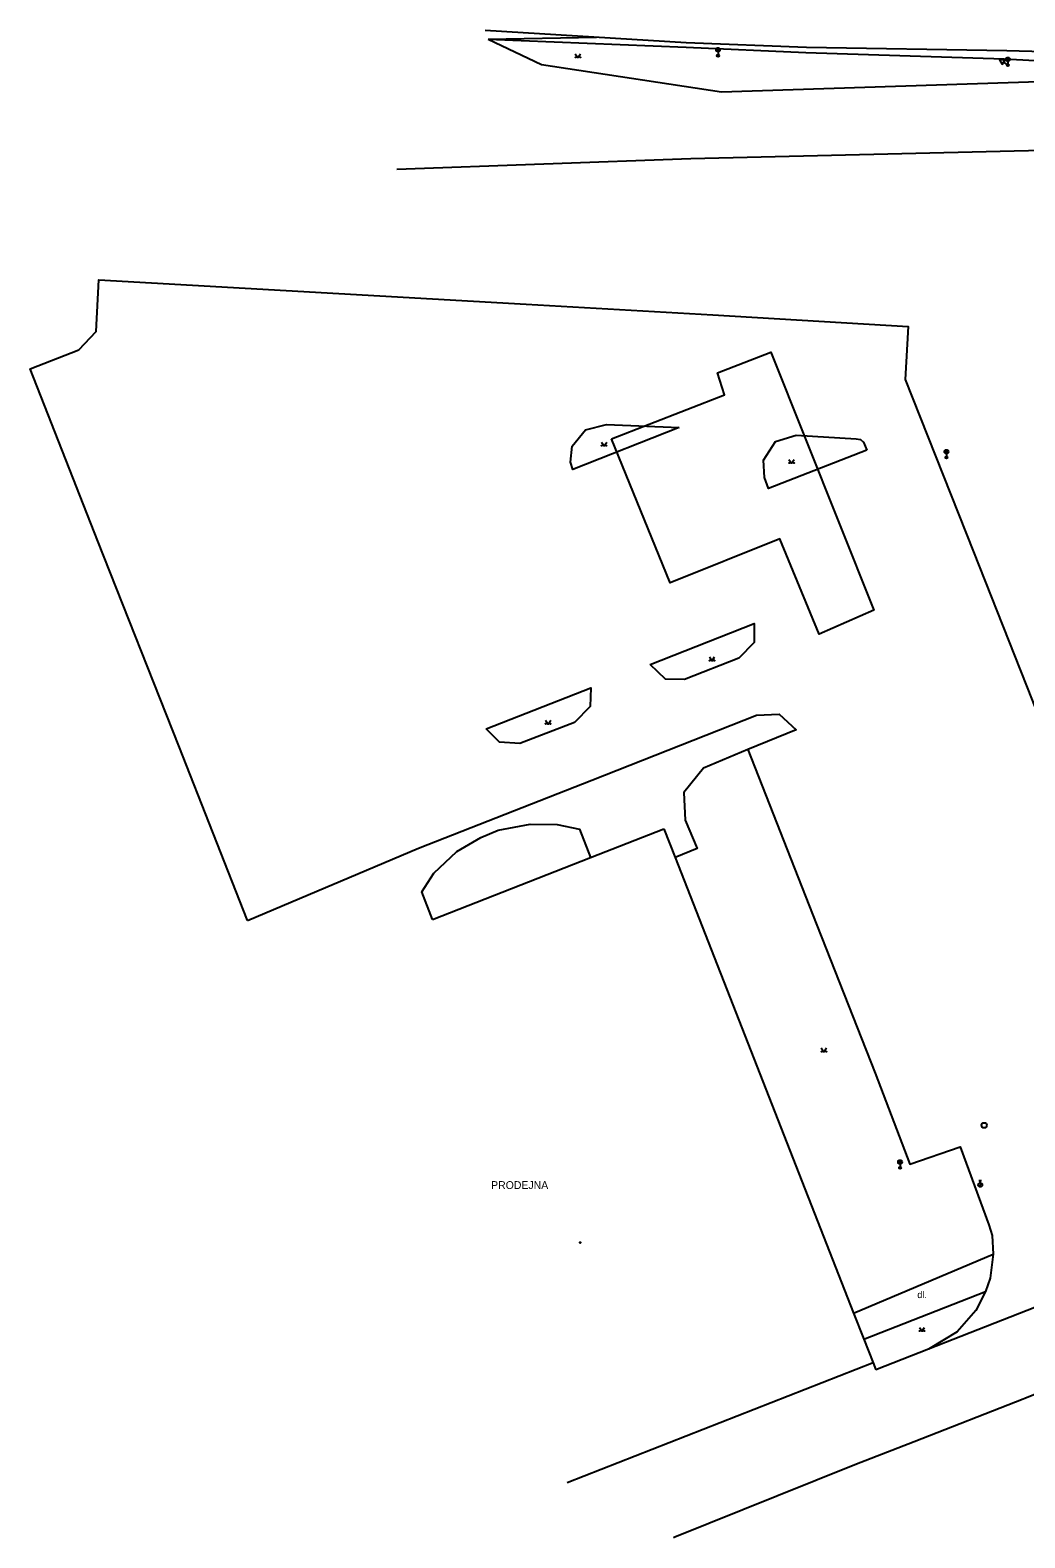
# Model space of a CAD drawing. Extents: x -602419 to -601554, y -1162937 to -1162362.
# Drawn here: x -602409.7 to -602314.6, y -1162869.2 to -1162725.1 of the extents above; entities that cross this region are included whole.
import ezdxf

# ---------------------------------------------------------------- set-up
doc = ezdxf.new("R2010")
doc.units = 0
doc.layers.add('Podklad', color=7, linetype='Continuous')

msp = doc.modelspace()

# ---------------------------------------------------------------- linework, layer by layer
at = {"layer": 'Podklad'}
for p, q in [((-602344.0925, -1162727.1), (-602343.8275, -1162726.835)), ((-602344.0925, -1162726.835), (-602343.8275, -1162727.1)), ((-602343.96, -1162727.155), (-602343.96, -1162727.53)), ((-602316.6789, -1162728.1659), (-602316.25, -1162728.44)), ((-602316.3825, -1162728.01), (-602316.1175, -1162727.745)), ((-602316.3825, -1162727.745), (-602316.1175, -1162728.01)), ((-602316.25, -1162728.065), (-602316.25, -1162728.44)), ((-602322.2625, -1162765.52), (-602321.9975, -1162765.255)), ((-602322.2625, -1162765.255), (-602321.9975, -1162765.52)), ((-602322.13, -1162765.575), (-602322.13, -1162765.95)), ((-602326.6925, -1162833.43), (-602326.4275, -1162833.165)), ((-602326.6925, -1162833.165), (-602326.4275, -1162833.43)), ((-602326.56, -1162833.485), (-602326.56, -1162833.86)), ((-602319.019, -1162835.626), (-602318.754, -1162835.361)), ((-602319.015, -1162835.0525), (-602318.765, -1162835.0525)), ((-602318.89, -1162835.3025), (-602318.89, -1162835.0525))]:
    msp.add_line(p, q, dxfattribs=at)
for points in [[(-602366.2199, -1162725.09), (-602346.99, -1162726.28), (-602335.5, -1162726.7199), (-602316.36, -1162727.02), (-602312.77, -1162727.14), (-602310.06, -1162728.28), (-602308.75, -1162729.84)], [(-602309.36, -1162729.86), (-602311.21, -1162728.65), (-602313.63, -1162728.03), (-602316.6, -1162727.87), (-602335.56, -1162727.26), (-602347, -1162726.75), (-602365.93, -1162725.9699)], [(-602365.9155, -1162725.9599), (-602355.5696, -1162725.7491)], [(-602365.9155, -1162725.9599), (-602360.83, -1162728.3839), (-602343.64, -1162730.9839), (-602309.36, -1162729.8599), (-602308.75, -1162729.84)], [(-602357.6, -1162727.3449), (-602357.35, -1162727.7199), (-602357.1, -1162727.3449)], [(-602304.89, -1162736.39), (-602346.56, -1162737.4)], [(-602346.56, -1162737.4), (-602374.65, -1162738.4)], [(-602388.93, -1162810.2), (-602395.51, -1162793.5), (-602403.24, -1162773.94), (-602409.71, -1162757.48), (-602405.07, -1162755.65), (-602403.4, -1162753.9), (-602403.15, -1162748.96), (-602362.29, -1162751.3), (-602344.45, -1162752.32), (-602325.79, -1162753.42), (-602326.07, -1162758.48), (-602319.53, -1162774.95), (-602313.93, -1162789.1599), (-602309.68, -1162800.1599), (-602304.38, -1162813.56), (-602300.54, -1162823.33)], [(-602354.13, -1162764.17), (-602343.33, -1162759.96), (-602344.02, -1162757.84), (-602338.9, -1162755.88), (-602329.05, -1162780.53), (-602334.3, -1162782.83), (-602338.04, -1162773.72), (-602348.54, -1162777.93), (-602354.13, -1162764.17)], [(-602347.67, -1162763.09), (-602357.83, -1162767.1), (-602358.07, -1162766.4), (-602357.9, -1162764.86), (-602356.64, -1162763.3), (-602354.63, -1162762.8), (-602347.67, -1162763.09)], [(-602329.7199, -1162765.26), (-602339.12, -1162768.9), (-602339.53, -1162767.86), (-602339.6, -1162766.2), (-602338.45, -1162764.42), (-602336.49, -1162763.8), (-602330.75, -1162764.1599), (-602330.34, -1162764.24), (-602330.05, -1162764.48), (-602329.7199, -1162765.26)], [(-602355.1, -1162764.465), (-602354.85, -1162764.84), (-602354.6, -1162764.465)], [(-602337.18, -1162766.125), (-602336.93, -1162766.5), (-602336.68, -1162766.125)], [(-602350.45, -1162785.7199), (-602340.5, -1162781.8), (-602340.5, -1162783.64), (-602341.96, -1162785.12), (-602347.1599, -1162787.1599), (-602348.98, -1162787.14), (-602350.45, -1162785.7199)], [(-602344.78, -1162785.005), (-602344.53, -1162785.38), (-602344.28, -1162785.005)], [(-602366.13, -1162791.88), (-602356.13, -1162787.96), (-602356.18, -1162789.76), (-602357.68, -1162791.28), (-602362.9, -1162793.28), (-602364.85, -1162793.1599), (-602366.13, -1162791.88)], [(-602388.93, -1162810.2), (-602372.6, -1162803.28), (-602356.02, -1162796.78), (-602340.27, -1162790.58), (-602338.12, -1162790.48), (-602336.5, -1162791.98), (-602341.12, -1162793.86)], [(-602360.45, -1162791.055), (-602360.2, -1162791.43), (-602359.95, -1162791.055)], [(-602341.12, -1162793.86), (-602345.34, -1162795.64), (-602347.23, -1162797.98), (-602347.09, -1162800.62), (-602345.95, -1162803.34), (-602348.05, -1162804.2)], [(-602341.12, -1162793.86), (-602334.94, -1162809.6), (-602328.95, -1162824.81), (-602325.64, -1162833.5), (-602320.82, -1162831.84), (-602318.07, -1162839.31), (-602317.77, -1162840.31), (-602317.6599, -1162842.12)], [(-602371.24, -1162810.13), (-602372.27, -1162807.47), (-602371.12, -1162805.7), (-602368.92, -1162803.62), (-602366.62, -1162802.26), (-602364.97, -1162801.56), (-602361.92, -1162800.99), (-602359.34, -1162801.04), (-602357.19, -1162801.47), (-602356.16, -1162804.2)], [(-602356.16, -1162804.2), (-602349.13, -1162801.44)], [(-602349.13, -1162801.44), (-602348.05, -1162804.2)], [(-602371.24, -1162810.13), (-602356.16, -1162804.2)], [(-602348.05, -1162804.2), (-602331, -1162847.74)], [(-602334.09, -1162822.395), (-602333.84, -1162822.77), (-602333.59, -1162822.395)], [(-602331, -1162847.74), (-602317.6599, -1162842.12)], [(-602300.26, -1162841.94), (-602323.84, -1162851.19)], [(-602317.6599, -1162842.12), (-602317.93, -1162844.4)], [(-602317.93, -1162844.4), (-602318.39, -1162845.69)], [(-602291.4, -1162846.37), (-602291.67, -1162846.5), (-602291.63, -1162846.58), (-602295.39, -1162848.31), (-602307.21, -1162852.94), (-602312.92, -1162855.22), (-602314.63, -1162855.9), (-602314.79, -1162855.96), (-602325.2, -1162860.06), (-602330.89, -1162862.26), (-602338.35, -1162865.25), (-602348.1, -1162869.18), (-602348.22, -1162869.23)], [(-602330.02, -1162850.25), (-602318.39, -1162845.69)], [(-602318.39, -1162845.69), (-602319.3, -1162847.48), (-602321.09, -1162849.54), (-602323.84, -1162851.19), (-602328.87, -1162853.18)], [(-602331, -1162847.74), (-602330.02, -1162850.25)], [(-602324.71, -1162849.105), (-602324.46, -1162849.48), (-602324.21, -1162849.105)], [(-602330.02, -1162850.25), (-602329.13, -1162852.51)], [(-602329.13, -1162852.51), (-602358.38, -1162863.96)], [(-602329.13, -1162852.51), (-602328.87, -1162853.18)]]:
    msp.add_lwpolyline(points, dxfattribs=at)
msp.add_lwpolyline([(-602316.8135, -1162728.3766), (-602316.5443, -1162727.9553), (-602317.0438, -1162727.9328)], close=True, dxfattribs=at)
for centre, radius in [((-602343.96, -1162726.9675), 0.1875), ((-602357.5751, -1162727.6948), 0.025), ((-602357.1254, -1162727.6948), 0.025), ((-602343.96, -1162727.53), 0.1), ((-602343.96, -1162727.53), 0.0723), ((-602343.96, -1162727.53), 0.0438), ((-602316.25, -1162727.8775), 0.1875), ((-602316.25, -1162728.44), 0.1), ((-602316.25, -1162728.44), 0.0723), ((-602316.25, -1162728.44), 0.0438), ((-602355.0751, -1162764.8149), 0.025), ((-602354.6254, -1162764.8149), 0.025), ((-602322.13, -1162765.3875), 0.1875), ((-602337.1551, -1162766.4749), 0.025), ((-602336.7054, -1162766.4749), 0.025), ((-602322.13, -1162765.95), 0.1), ((-602322.13, -1162765.95), 0.0723), ((-602322.13, -1162765.95), 0.0438), ((-602344.7551, -1162785.3549), 0.025), ((-602344.3054, -1162785.3549), 0.025), ((-602360.4251, -1162791.4049), 0.025), ((-602359.9754, -1162791.4049), 0.025), ((-602334.0651, -1162822.7449), 0.025), ((-602333.6154, -1162822.7449), 0.025), ((-602318.52, -1162829.79), 0.25), ((-602326.56, -1162833.2975), 0.1875), ((-602326.56, -1162833.86), 0.1), ((-602326.56, -1162833.86), 0.0723), ((-602326.56, -1162833.86), 0.0438), ((-602318.89, -1162835.49), 0.1875), ((-602357.14, -1162841), 0.045), ((-602357.14, -1162841), 0.0199), ((-602324.6851, -1162849.4549), 0.025), ((-602324.2354, -1162849.4549), 0.025)]:
    msp.add_circle(centre, radius, dxfattribs=at)

# ---------------------------------------------------------------- texts
for s, height, p in [('PRODEJNA', 0.75, (-602365.65, -1162835.88)), ('dl.', 0.65, (-602324.9099, -1162846.31))]:
    msp.add_text(s, height=height, dxfattribs=at).set_placement(p)

doc.saveas('drawing.dxf')
